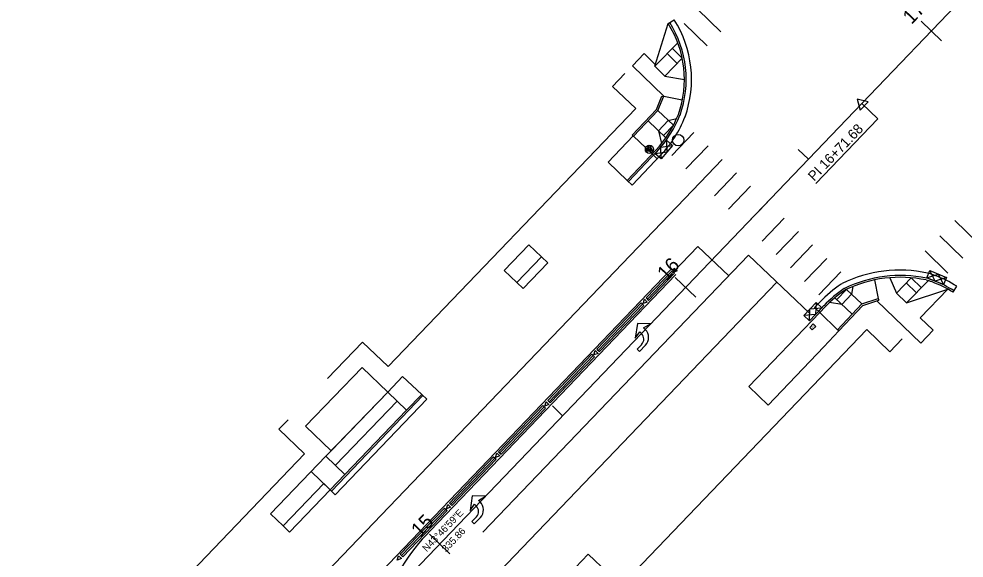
# Model space of a CAD drawing. Extents: x 2377903 to 2496516, y 664638 to 732785.
# Drawn here: x 2378138.2 to 2378404.2, y 730451.4 to 730603.2 of the extents above; entities that cross this region are included whole.
import ezdxf

# ---------------------------------------------------------------- set-up
doc = ezdxf.new("R2010")
doc.units = 0
for name, color, linetype in [('ALG_CL_BLUE_Horiz', 7, 'Continuous'), ('ALG_CL_BLUE_Horiz-PC-PT-PI', 7, 'Continuous'), ('ALG_CL_BLUE_Horiz-Stationing', 7, 'Continuous'), ('ALG_CL_BLUE_Horiz-Text', 7, 'Continuous'), ('Default', 7, 'Continuous'), ('DES_ROADWAY_Approach', 7, 'Continuous'), ('DES_ROADWAY_Curb-Back', 7, 'Continuous'), ('DES_ROADWAY_Curb-Face', 7, 'Continuous'), ('DES_ROADWAY_Curb-Face-LINE STYLE', 7, 'Continuous'), ('DES_ROADWAY_Edge-of-Pavement', 7, 'Continuous'), ('DES_ROADWAY_Sidewalk', 7, 'Continuous'), ('ENV_EROSN_Temp-Erosn-Ctrl-Details', 7, 'Continuous'), ('ROW_P_PUA', 7, 'Continuous'), ('TOPO_WTRUTIL_Valve', 7, 'Continuous'), ('TRAF_PAVEMARK_Arrows', 7, 'Continuous'), ('TRAF_PAVEMARK_Stop-Bar', 7, 'Continuous'), ('TRAF_PAVEMARK_White_8-IN', 7, 'Continuous'), ('TRAF_PAVEMARK_White_SKIP 12-38', 7, 'Continuous'), ('TRAF_PAVEMARK_Yellow', 7, 'Continuous'), ('TRAF_PAVEMARK_Yellow-DBL YELLOW', 7, 'Continuous'), ('TRAF_SIGNAL_Composite-Junction-Box', 7, 'Continuous'), ('TRAF_WORKZONE_Drum', 7, 'Continuous'), ('UTIL_STORM_Manhole', 7, 'Continuous')]:
    doc.layers.add(name, color=color, linetype=linetype)

# ---------------------------------------------------------------- blocks, each defined once
blk = doc.blocks.new('MWL_2')
at = {"layer": 'Default'}
for p, q in [((-0.76, -0.44), (0, 0.88)), ((-0.41, -0.23), (0, 0.47)), ((0, 0.88), (0.76, -0.44)), ((0, 0.47), (0.41, -0.23)), ((0.76, -0.44), (-0.76, -0.44)), ((0.41, -0.23), (-0.41, -0.23))]:
    blk.add_line(p, q, dxfattribs=at)
blk.add_circle((0, 0), 0.883, dxfattribs=at)
for start, end in [(360, 180), (180, 360)]:
    blk.add_arc((0, 0), 0.0254, start, end, dxfattribs=at)
blk = doc.blocks.new('JCTBOX_5')
at = {"layer": 'Default'}
for p, q in [((-0.0086, 0.0064), (0.0086, 0.0064)), ((-0.0086, 0.0064), (-0.0086, -0.0064)), ((0.0086, 0.0064), (0.0086, -0.0064)), ((-0.0086, -0.0064), (0.0086, -0.0064))]:
    blk.add_line(p, q, dxfattribs=at)
blk.add_text('SIG', height=0.00635, dxfattribs=at).set_placement((-0.0063, -0.0031))

msp = doc.modelspace()

# ---------------------------------------------------------------- linework, layer by layer
at = {"layer": 'ALG_CL_BLUE_Horiz'}
for p, q in [((2378375.43, 730579.33), (2378840.27, 731064.93)), ((2378143.04, 730336.85), (2378375.43, 730579.33))]:
    msp.add_line(p, q, dxfattribs=at)
at = {"layer": 'ALG_CL_BLUE_Horiz-PC-PT-PI'}
for p, q in [((2378375.43, 730579.33), (2378379.93, 730575.03)), ((2378379.93, 730575.03), (2378362.53, 730556.85))]:
    msp.add_line(p, q, dxfattribs=at)
at = {"layer": 'ALG_CL_BLUE_Horiz-Stationing'}
for p, q in [((2378392.12, 730602.55), (2378397.9, 730597.02)), ((2378357.54, 730566.44), (2378360.43, 730563.68)), ((2378322.95, 730530.35), (2378328.72, 730524.81)), ((2378288.35, 730494.25), (2378291.24, 730491.48)), ((2378253.75, 730458.15), (2378259.53, 730452.61))]:
    msp.add_line(p, q, dxfattribs=at)
msp.add_lwpolyline([(2378374.1, 730580.61), (2378374.99, 730577.54), (2378377.21, 730579.85)], close=True, dxfattribs=at)
at = {"layer": 'Default'}
msp.add_line((2378227.3, 730477.52), (2378244.66, 730495.6), dxfattribs=at)
at = {"layer": 'DES_ROADWAY_Approach'}
for points in [[(2378287.07, 730534.49), (2378280.15, 730527.27), (2378278.34, 730529.01), (2378285.26, 730536.23)], [(2378242, 730498.15), (2378242, 730498.15), (2378226.11, 730481.63), (2378218.89, 730488.55), (2378218.89, 730488.55), (2378234.79, 730505.09)], [(2378212.6, 730460.43), (2378224.01, 730472.36), (2378225.82, 730470.63), (2378214.4, 730458.7)]]:
    msp.add_lwpolyline(points, close=True, dxfattribs=at)
at = {"layer": 'DES_ROADWAY_Curb-Back'}
for p, q in [((2378309.38, 730557.74), (2378317.46, 730566.28)), ((2378322.38, 730531.93), (2378315.08, 730524.31)), ((2378313.7, 730522.87), (2378301.24, 730509.87)), ((2378363.59, 730520.51), (2378365.13, 730522.12)), ((2378299.86, 730508.43), (2378287.4, 730495.43)), ((2378286.02, 730493.99), (2378273.57, 730480.99)), ((2378272.18, 730479.55), (2378259.73, 730466.55)), ((2378258.34, 730465.11), (2378245.89, 730452.11))]:
    msp.add_line(p, q, dxfattribs=at)
msp.add_lwpolyline([(2378225.82, 730470.63), (2378229.97, 730474.96), (2378247.32, 730493.05), (2378251.57, 730497.48)], dxfattribs=at)
for centre, radius, start, end in [((2378296.19, 730586.16), 29.32, 340.3381, 32.3962), ((2378295.04, 730587.49), 30.86, 316.5834, 338.7337), ((2378386.23, 730495.09), 35.36, 78.1053, 115.985), ((2378391.81, 730521.6), 8.26, 65.6091, 78.1053), ((2378384.56, 730499.98), 31.04, 57.7205, 69.904), ((2378390.8, 730497.52), 35.55, 124.3593, 136.2315)]:
    msp.add_arc(centre, radius, start, end, dxfattribs=at)
at = {"layer": 'DES_ROADWAY_Curb-Face'}
for p, q in [((2378322.02, 730532.27), (2378314.72, 730524.65)), ((2378322.75, 730531.58), (2378315.44, 730523.96)), ((2378322.02, 730532.27), (2378322.75, 730531.58)), ((2378314.72, 730524.65), (2378315.44, 730523.96)), ((2378313.34, 730523.21), (2378300.88, 730510.22)), ((2378314.06, 730522.52), (2378301.6, 730509.52)), ((2378313.34, 730523.21), (2378314.06, 730522.52)), ((2378300.88, 730510.22), (2378301.6, 730509.52)), ((2378299.5, 730508.77), (2378287.04, 730495.78)), ((2378300.22, 730508.08), (2378287.77, 730495.08)), ((2378299.5, 730508.77), (2378300.22, 730508.08)), ((2378285.66, 730494.33), (2378273.21, 730481.34)), ((2378285.66, 730494.33), (2378286.38, 730493.64)), ((2378287.04, 730495.78), (2378287.77, 730495.08)), ((2378286.38, 730493.64), (2378273.93, 730480.65)), ((2378273.21, 730481.34), (2378273.93, 730480.65)), ((2378271.82, 730479.89), (2378259.37, 730466.9)), ((2378272.54, 730479.2), (2378260.09, 730466.21)), ((2378271.82, 730479.89), (2378272.54, 730479.2)), ((2378257.98, 730465.45), (2378245.53, 730452.46)), ((2378257.98, 730465.45), (2378258.7, 730464.76)), ((2378259.37, 730466.9), (2378260.09, 730466.21)), ((2378258.7, 730464.76), (2378246.25, 730451.77)), ((2378245.53, 730452.46), (2378246.25, 730451.77))]:
    msp.add_line(p, q, dxfattribs=at)
at = {"layer": 'DES_ROADWAY_Curb-Face-LINE STYLE'}
for p, q in [((2378309.74, 730557.4), (2378317.82, 730565.94)), ((2378364.76, 730522.46), (2378363.23, 730520.86)), ((2378226.18, 730470.28), (2378251.93, 730497.13))]:
    msp.add_line(p, q, dxfattribs=at)
for points in [[(2378324.26, 730576.11), (2378324.27, 730576.12), (2378324.27, 730576.13)], [(2378370.52, 730527.32), (2378370.48, 730527.31), (2378370.45, 730527.29)]]:
    msp.add_lwpolyline(points, dxfattribs=at)
for centre, radius, start, end in [((2378296.19, 730586.16), 29.82, 340.3381, 32.3961), ((2378295.04, 730587.49), 31.36, 316.5834, 338.7337), ((2378386.23, 730495.09), 35.86, 78.1053, 115.985), ((2378391.81, 730521.6), 8.76, 65.733, 78.1053), ((2378384.56, 730499.98), 31.54, 57.7205, 69.8703), ((2378390.8, 730497.52), 36.05, 124.3593, 136.2315)]:
    msp.add_arc(centre, radius, start, end, dxfattribs=at)
at = {"layer": 'DES_ROADWAY_Edge-of-Pavement'}
for p, q in [((2378320.94, 730601.87), (2378322.63, 730602.94)), ((2378310.83, 730556.37), (2378318.91, 730564.91)), ((2378316.41, 730565.18), (2378317.86, 730563.8)), ((2378309.38, 730557.74), (2378310.83, 730556.37)), ((2378401.13, 730526.22), (2378402.2, 730527.91)), ((2378362.15, 730521.9), (2378363.68, 730523.5)), ((2378363.59, 730520.51), (2378362.15, 730521.9)), ((2378251.57, 730497.48), (2378253.01, 730496.09)), ((2378227.26, 730469.24), (2378253.01, 730496.09)), ((2378225.82, 730470.63), (2378227.26, 730469.24))]:
    msp.add_line(p, q, dxfattribs=at)
for points in [[(2378325.66, 730575.57), (2378325.67, 730575.6), (2378325.68, 730575.62)], [(2378369.61, 730528.52), (2378369.73, 730528.61), (2378369.86, 730528.67)]]:
    msp.add_lwpolyline(points, dxfattribs=at)
for centre, radius, start, end in [((2378296.19, 730586.16), 31.32, 340.3381, 32.3961), ((2378295.04, 730587.49), 32.86, 316.5834, 338.7337), ((2378386.23, 730495.09), 37.36, 78.1053, 115.985), ((2378391.81, 730521.6), 10.26, 66.044, 78.1053), ((2378384.56, 730499.98), 33.04, 57.7205, 69.779), ((2378390.8, 730497.52), 37.55, 124.3593, 136.2315)]:
    msp.add_arc(centre, radius, start, end, dxfattribs=at)
at = {"layer": 'DES_ROADWAY_Sidewalk'}
for p, q in [((2378317.14, 730589.92), (2378320.94, 730601.87)), ((2378323.62, 730596.5), (2378317.14, 730589.92)), ((2378310.86, 730589.97), (2378314.15, 730593.41)), ((2378317.29, 730590.4), (2378314.15, 730593.41)), ((2378320.65, 730593.48), (2378323.5, 730590.67)), ((2378322.05, 730594.91), (2378324.9, 730592.1)), ((2378319.73, 730581.47), (2378310.86, 730589.97)), ((2378317.14, 730589.92), (2378319.99, 730587.11)), ((2378324.9, 730592.1), (2378319.99, 730587.11)), ((2378319.99, 730587.11), (2378325.51, 730586.13)), ((2378317.64, 730577.65), (2378319.19, 730581.45)), ((2378318.06, 730577.38), (2378319.73, 730581.47)), ((2378319.19, 730581.45), (2378319.69, 730581.35)), ((2378324.91, 730580.28), (2378319.69, 730581.35)), ((2378310.85, 730570.5), (2378317.64, 730577.65)), ((2378311.21, 730570.16), (2378318.06, 730577.38)), ((2378318.06, 730577.38), (2378322.42, 730573.25)), ((2378315.31, 730574.48), (2378320.29, 730569.75)), ((2378318.21, 730571.72), (2378320.97, 730574.63)), ((2378320.97, 730574.63), (2378323.32, 730575.15)), ((2378318.21, 730571.72), (2378319.08, 730568.14)), ((2378319.66, 730570.35), (2378322.42, 730573.25)), ((2378304.03, 730562.85), (2378311.11, 730570.26)), ((2378310.85, 730570.5), (2378311.21, 730570.16)), ((2378316.41, 730565.18), (2378311.21, 730570.16)), ((2378309.38, 730557.74), (2378304.03, 730562.85)), ((2378281.74, 730539.6), (2378274.82, 730532.38)), ((2378285.26, 730536.23), (2378281.74, 730539.6)), ((2378278.34, 730529.01), (2378285.26, 730536.23)), ((2378278.34, 730529.01), (2378274.82, 730532.38)), ((2378378.98, 730529.7), (2378380.07, 730524.51)), ((2378383.35, 730530.33), (2378385.15, 730526.02)), ((2378385.15, 730526.02), (2378389.35, 730530.31)), ((2378390.81, 730526.08), (2378387.95, 730528.88)), ((2378388.01, 730523.22), (2378394.17, 730529.52)), ((2378392.21, 730527.51), (2378389.35, 730530.31)), ((2378368.36, 730524.15), (2378371.11, 730527.05)), ((2378371.11, 730527.05), (2378375.47, 730522.93)), ((2378372.94, 730527.86), (2378372.56, 730525.68)), ((2378388.01, 730523.22), (2378399.66, 730527.1)), ((2378391.9, 730519), (2378399.66, 730527.1)), ((2378367.83, 730524.66), (2378372.71, 730520.02)), ((2378369.81, 730522.78), (2378372.56, 730525.68)), ((2378375.47, 730522.93), (2378380.07, 730524.51)), ((2378375.74, 730522.49), (2378380.23, 730524.04)), ((2378379.63, 730523.83), (2378392.05, 730511.93)), ((2378380.07, 730524.51), (2378380.23, 730524.04)), ((2378388.01, 730523.22), (2378385.15, 730526.02)), ((2378369.81, 730522.78), (2378366.34, 730523.32)), ((2378368.61, 730515.7), (2378375.47, 730522.93)), ((2378368.97, 730515.35), (2378375.74, 730522.49)), ((2378343.63, 730499.67), (2378363.59, 730520.51)), ((2378363.59, 730520.51), (2378368.61, 730515.7)), ((2378391.9, 730519), (2378395.51, 730515.54)), ((2378368.97, 730515.35), (2378368.61, 730515.7)), ((2378392.05, 730511.93), (2378395.51, 730515.54)), ((2378364.75, 730510.87), (2378368.97, 730515.35)), ((2378364.75, 730510.87), (2378349.06, 730494.46)), ((2378242, 730498.15), (2378246.15, 730502.49)), ((2378246.15, 730502.49), (2378251.57, 730497.48)), ((2378349.06, 730494.46), (2378343.63, 730499.67)), ((2378224.62, 730480.08), (2378242, 730498.15)), ((2378242, 730498.15), (2378247.32, 730493.05)), ((2378224.62, 730480.08), (2378209.05, 730463.83)), ((2378224.62, 730480.08), (2378229.97, 730474.96)), ((2378220.47, 730475.75), (2378225.82, 730470.63)), ((2378212.6, 730460.43), (2378224.01, 730472.36)), ((2378212.6, 730460.43), (2378209.05, 730463.83)), ((2378298.45, 730452.52), (2378294.84, 730448.74)), ((2378303.92, 730447.28), (2378298.45, 730452.52))]:
    msp.add_line(p, q, dxfattribs=at)
at = {"layer": 'ENV_EROSN_Temp-Erosn-Ctrl-Details'}
for points in [[(2378322.16, 730567.59), (2378318.93, 730563.77), (2378317.25, 730565.19), (2378320.48, 730569.01)], [(2378398.38, 730528.38), (2378393.77, 730530.3), (2378394.62, 730532.33), (2378399.23, 730530.41)], [(2378364.14, 730521.81), (2378360.68, 730518.2), (2378359.1, 730519.72), (2378362.55, 730523.34)]]:
    msp.add_lwpolyline(points, close=True, dxfattribs=at)
for points in [[(2378320.48, 730569.01), (2378320.54, 730565.68), (2378317.25, 730565.19)], [(2378318.93, 730563.77), (2378318.86, 730567.1), (2378322.16, 730567.59)], [(2378393.77, 730530.3), (2378396.92, 730531.37), (2378398.38, 730528.38)], [(2378399.23, 730530.41), (2378396.08, 730529.34), (2378394.62, 730532.33)], [(2378362.55, 730523.34), (2378362.41, 730520.01), (2378359.1, 730519.72)], [(2378360.68, 730518.2), (2378360.82, 730521.53), (2378364.14, 730521.81)]]:
    msp.add_lwpolyline(points, dxfattribs=at)
at = {"layer": 'ROW_P_PUA'}
for p, q in [((2378305.3, 730584.19), (2378308.75, 730587.8)), ((2378311.79, 730577.97), (2378305.3, 730584.19)), ((2378242.14, 730505.29), (2378311.79, 730577.97)), ((2378303.66, 730439.41), (2378376.8, 730515.72)), ((2378376.8, 730515.72), (2378383.29, 730509.49)), ((2378383.29, 730509.49), (2378386.76, 730513.1)), ((2378225.05, 730501.91), (2378234.92, 730512.21)), ((2378234.92, 730512.21), (2378242.14, 730505.29)), ((2378211.4, 730487.66), (2378213.98, 730490.36)), ((2378211.41, 730487.65), (2378218.62, 730480.74)), ((2378138.22, 730396.85), (2378218.62, 730480.74))]:
    msp.add_line(p, q, dxfattribs=at)
at = {"layer": 'TOPO_WTRUTIL_Valve'}
msp.add_circle((2378323.74, 730569.07), 1.6, dxfattribs=at)
at = {"layer": 'TRAF_PAVEMARK_Arrows'}
for p, q in [((2378312.26, 730517.46), (2378311.69, 730513.27)), ((2378316, 730517.31), (2378312.26, 730517.46)), ((2378314.04, 730516.18), (2378316, 730517.31)), ((2378314.49, 730515.75), (2378314.04, 730516.18)), ((2378311.69, 730513.27), (2378312.97, 730515.06)), ((2378312.97, 730515.06), (2378313.42, 730514.63)), ((2378313.48, 730511.55), (2378312.19, 730510.21)), ((2378312.19, 730510.21), (2378312.87, 730509.57)), ((2378312.87, 730509.57), (2378314.58, 730511.36)), ((2378265.76, 730468.93), (2378265.19, 730464.75)), ((2378269.49, 730468.79), (2378265.76, 730468.93)), ((2378267.54, 730467.65), (2378269.49, 730468.79)), ((2378267.99, 730467.22), (2378267.54, 730467.65)), ((2378265.19, 730464.75), (2378266.47, 730466.53)), ((2378266.47, 730466.53), (2378266.91, 730466.1)), ((2378266.98, 730463.03), (2378265.69, 730461.69)), ((2378266.36, 730461.04), (2378268.08, 730462.83)), ((2378265.69, 730461.69), (2378266.36, 730461.04))]:
    msp.add_line(p, q, dxfattribs=at)
for centre, radius in [((2378312.34, 730513.5), 3.1), ((2378311.91, 730513.06), 2.17), ((2378265.41, 730464.53), 2.17), ((2378265.84, 730464.98), 3.1)]:
    msp.add_arc(centre, radius, 316.2016, 46.2016, dxfattribs=at)
at = {"layer": 'TRAF_PAVEMARK_Stop-Bar'}
for p, q in [((2378335.73, 730599.53), (2378329.32, 730605.85)), ((2378331.87, 730595.61), (2378325.46, 730601.93)), ((2378321.96, 730564.72), (2378328.19, 730571.22)), ((2378325.95, 730560.94), (2378332.18, 730567.44)), ((2378329.94, 730557.15), (2378336.17, 730563.65)), ((2378333.93, 730553.37), (2378340.16, 730559.87)), ((2378337.92, 730549.58), (2378344.15, 730556.08)), ((2378342.64, 730545.11), (2378348.86, 730551.61)), ((2378347.35, 730540.64), (2378353.58, 730547.13)), ((2378408.05, 730540.15), (2378401.61, 730546.44)), ((2378351.34, 730536.85), (2378357.57, 730543.35)), ((2378403.85, 730535.86), (2378397.42, 730542.15)), ((2378355.33, 730533.07), (2378361.56, 730539.56)), ((2378329.3, 730539.15), (2378338.01, 730530.89)), ((2378399.66, 730531.57), (2378393.22, 730537.86)), ((2378343.55, 730536.67), (2378360.75, 730520.35)), ((2378359.32, 730529.28), (2378365.55, 730535.78)), ((2378363.31, 730525.49), (2378369.54, 730531.99))]:
    msp.add_line(p, q, dxfattribs=at)
at = {"layer": 'TRAF_PAVEMARK_White_8-IN'}
msp.add_line((2378343.55, 730536.67), (2378268.82, 730458.69), dxfattribs=at)
at = {"layer": 'TRAF_PAVEMARK_White_SKIP 12-38'}
for p, q in [((2378329.94, 730557.15), (2378210.52, 730432.55)), ((2378351.49, 730529.06), (2378235.84, 730408.38))]:
    msp.add_line(p, q, dxfattribs=at)
at = {"layer": 'TRAF_PAVEMARK_Yellow'}
for p, q in [((2378321.66, 730532.62), (2378218.56, 730425.04)), ((2378323.11, 730531.24), (2378253.91, 730459.04))]:
    msp.add_line(p, q, dxfattribs=at)
msp.add_arc((2378292.72, 730420.41), 54.76, 135.1259, 162.0922, dxfattribs=at)
at = {"layer": 'TRAF_PAVEMARK_Yellow-DBL YELLOW'}
msp.add_line((2378329.3, 730539.15), (2378322.38, 730531.93), dxfattribs=at)
at = {"layer": 'TRAF_WORKZONE_Drum'}
for points in [[(2378322.3, 730531.84), (2378322.67, 730533.04), (2378323.48, 730532.26)], [(2378313.87, 730523.05), (2378314.24, 730524.25), (2378315.06, 730523.47)], [(2378300.03, 730508.61), (2378300.41, 730509.81), (2378301.22, 730509.03)], [(2378286.19, 730494.17), (2378286.57, 730495.37), (2378287.38, 730494.59)], [(2378272.36, 730479.73), (2378272.73, 730480.93), (2378273.54, 730480.15)], [(2378258.52, 730465.29), (2378258.89, 730466.49), (2378259.7, 730465.71)], [(2378244.68, 730450.85), (2378245.05, 730452.05), (2378245.86, 730451.27)]]:
    msp.add_lwpolyline(points, close=True, dxfattribs=at)

# ---------------------------------------------------------------- block references
at = {"layer": 'TRAF_SIGNAL_Composite-Junction-Box', "xscale": 78.74, "yscale": 78.74000000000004, "rotation": 45.60829090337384}
msp.add_blockref('JCTBOX_5', (2378361.62, 730516.47), dxfattribs=at)
at = {"layer": 'UTIL_STORM_Manhole', "xscale": 1.311021, "yscale": 1.311021}
msp.add_blockref('MWL_2', (2378315.67, 730566.49), dxfattribs=at)

# ---------------------------------------------------------------- texts
at = {"layer": 'ALG_CL_BLUE_Horiz-PC-PT-PI'}
msp.add_text('PI 16+71.68', height=2.8, rotation=46.2123, dxfattribs=at).set_placement((2378362.01, 730557.35))
at = {"layer": 'ALG_CL_BLUE_Horiz-Stationing'}
for s, rotation, p in [('17', 46.2512, (2378389.43, 730601.47)), ('16', 46.217, (2378320.33, 730529.35)), ('15', 46.217, (2378251.07, 730457.08))]:
    msp.add_text(s, height=4, rotation=rotation, dxfattribs=at).set_placement(p)
at = {"layer": 'ALG_CL_BLUE_Horiz-Text'}
for s, p in [('N43°46\'59"E', (2378252.99, 730453.02)), ('335.86', (2378258.44, 730452.92))]:
    msp.add_text(s, height=2, rotation=46.217, dxfattribs=at).set_placement(p)

doc.saveas('drawing.dxf')
